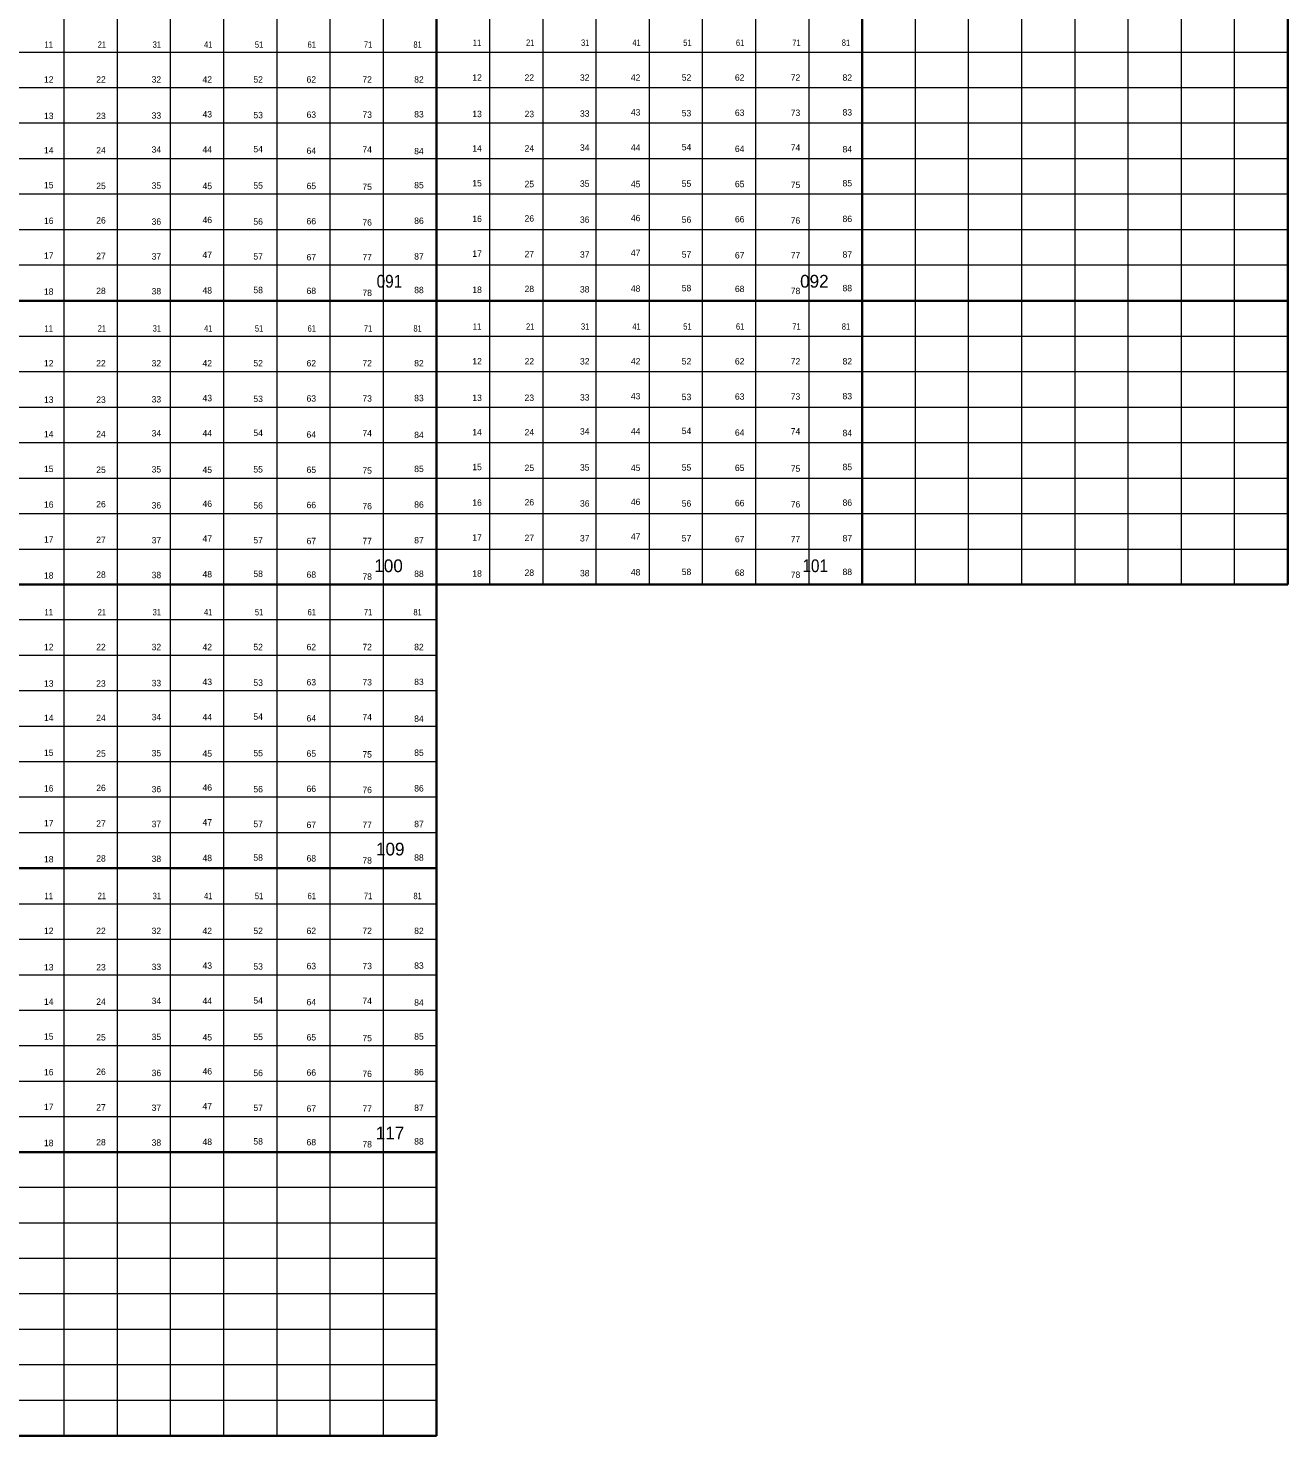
# Model space of a CAD drawing. Extents: x 639000 to 672000, y 222000 to 252000.
# Drawn here: x 660121 to 669000, y 224000 to 233921 of the extents above; entities that cross this region are included whole.
import ezdxf
from ezdxf.enums import TextEntityAlignment as Align

# ---------------------------------------------------------------- set-up
doc = ezdxf.new("R2010")
doc.units = 0
doc.header["$LTSCALE"] = 18
doc.layers.add('1', color=7, linetype='Continuous', lineweight=13)
doc.layers.add('2', color=7, linetype='Continuous')
doc.layers.add('29', color=7, linetype='Continuous')

msp = doc.modelspace()

# ---------------------------------------------------------------- linework, layer by layer
at = {"layer": '1'}
for p, q in [((660375, 224000), (660375, 246000)), ((660750, 224000), (660750, 246000)), ((661125, 224000), (661125, 246000)), ((661500, 224000), (661500, 246000)), ((661875, 224000), (661875, 246000)), ((662250, 224000), (662250, 246000)), ((662625, 224000), (662625, 246000)), ((663375, 230000), (663375, 244000)), ((663750, 230000), (663750, 244000)), ((664125, 230000), (664125, 244000)), ((664500, 230000), (664500, 244000)), ((664875, 230000), (664875, 244000)), ((665250, 230000), (665250, 244000)), ((665625, 230000), (665625, 244000)), ((666375, 230000), (666375, 242000)), ((666750, 230000), (666750, 242000)), ((667125, 230000), (667125, 242000)), ((667500, 230000), (667500, 242000)), ((667875, 230000), (667875, 242000)), ((668250, 230000), (668250, 242000)), ((668625, 230000), (668625, 242000)), ((669000, 233750), (642000, 233750)), ((669000, 233500), (642000, 233500)), ((669000, 233250), (642000, 233250)), ((669000, 233000), (642000, 233000)), ((669000, 232750), (642000, 232750)), ((669000, 232500), (642000, 232500)), ((669000, 232250), (642000, 232250)), ((642000, 231750), (669000, 231750)), ((642000, 231500), (669000, 231500)), ((642000, 231250), (669000, 231250)), ((642000, 231000), (669000, 231000)), ((642000, 230750), (669000, 230750)), ((642000, 230500), (669000, 230500)), ((642000, 230250), (669000, 230250)), ((663000, 229750), (642000, 229750)), ((663000, 229500), (642000, 229500)), ((663000, 229250), (642000, 229250)), ((663000, 229000), (642000, 229000)), ((663000, 228750), (642000, 228750)), ((663000, 228500), (642000, 228500)), ((663000, 228250), (642000, 228250)), ((642000, 227750), (663000, 227750)), ((642000, 227500), (663000, 227500)), ((642000, 227250), (663000, 227250)), ((642000, 227000), (663000, 227000)), ((642000, 226750), (663000, 226750)), ((642000, 226500), (663000, 226500)), ((642000, 226250), (663000, 226250)), ((663000, 225750), (642000, 225750)), ((663000, 225500), (642000, 225500)), ((663000, 225250), (642000, 225250)), ((663000, 225000), (642000, 225000)), ((663000, 224750), (642000, 224750)), ((663000, 224500), (642000, 224500)), ((663000, 224250), (642000, 224250))]:
    msp.add_line(p, q, dxfattribs=at)
at = {"layer": '1', "lineweight": 35}
for p, q in [((663000, 224000), (663000, 246000)), ((666000, 230000), (666000, 244000)), ((669000, 230000), (669000, 242000)), ((669000, 232000), (642000, 232000)), ((642000, 230000), (669000, 230000)), ((663000, 228000), (642000, 228000)), ((642000, 226000), (663000, 226000)), ((663000, 224000), (642000, 224000))]:
    msp.add_line(p, q, dxfattribs=at)

# ---------------------------------------------------------------- texts
at = {"layer": '2', "width": 0.9}
for s, p in [('091', (662667.19, 232091.88)), ('101', (665668.41, 230086.92))]:
    msp.add_text(s, height=90, rotation=359.94, dxfattribs=at).set_placement(p, align=Align.CENTER)
at = {"layer": '2'}
for s, p in [('092', (665662.55, 232091.88)), ('100', (662661.23, 230086.92))]:
    msp.add_text(s, height=90, rotation=359.94, dxfattribs=at).set_placement(p, align=Align.CENTER)
for s, p in [('109', (662673.03, 228090.19)), ('117', (662671.79, 226089.35))]:
    msp.add_text(s, height=90, dxfattribs=at).set_placement(p, align=Align.CENTER)
at = {"layer": '29', "width": 0.85}
for s, p in [('11', (663285.22, 233795.72)), ('21', (663659.82, 233795.72)), ('31', (664047.12, 233795.72)), ('41', (664409.03, 233795.72)), ('51', (664767.76, 233795.72)), ('61', (665139.19, 233795.72)), ('71', (665536.02, 233795.72)), ('81', (665885.22, 233795.72)), ('11', (660265.92, 233782.2)), ('21', (660640.53, 233782.2)), ('31', (661027.83, 233782.2)), ('41', (661389.73, 233782.2)), ('51', (661748.47, 233782.2)), ('61', (662119.89, 233782.2)), ('71', (662516.72, 233782.2)), ('81', (662865.93, 233782.2)), ('11', (660265.92, 231782.2)), ('21', (660640.53, 231782.2)), ('31', (661027.83, 231782.2)), ('41', (661389.73, 231782.2)), ('51', (661748.47, 231782.2)), ('61', (662119.89, 231782.2)), ('71', (662516.72, 231782.2)), ('81', (662865.93, 231782.2)), ('11', (663285.22, 231795.72)), ('21', (663659.82, 231795.72)), ('31', (664047.12, 231795.72)), ('41', (664409.03, 231795.72)), ('51', (664767.76, 231795.72)), ('61', (665139.19, 231795.72)), ('71', (665536.02, 231795.72)), ('81', (665885.22, 231795.72)), ('11', (660265.92, 229782.2)), ('21', (660640.53, 229782.2)), ('31', (661027.83, 229782.2)), ('41', (661389.73, 229782.2)), ('51', (661748.47, 229782.2)), ('61', (662119.89, 229782.2)), ('71', (662516.72, 229782.2)), ('81', (662865.93, 229782.2)), ('11', (660265.92, 227782.2)), ('21', (660640.53, 227782.2)), ('31', (661027.83, 227782.2)), ('41', (661389.73, 227782.2)), ('51', (661748.47, 227782.2)), ('61', (662119.89, 227782.2)), ('71', (662516.72, 227782.2)), ('81', (662865.93, 227782.2))]:
    msp.add_text(s, height=45, dxfattribs=at).set_placement(p, align=Align.CENTER)
at = {"layer": '29'}
for s, p in [('12', (660265.92, 233536.81)), ('22', (660634.18, 233536.81)), ('32', (661024.65, 233536.81)), ('42', (661383.38, 233536.81)), ('52', (661742.11, 233536.81)), ('62', (662116.72, 233536.81)), ('72', (662510.37, 233536.81)), ('82', (662875.45, 233536.81)), ('12', (663285.22, 233550.33)), ('22', (663653.47, 233550.33)), ('32', (664043.95, 233550.33)), ('42', (664402.68, 233550.33)), ('52', (664761.41, 233550.33)), ('62', (665136.01, 233550.33)), ('72', (665529.66, 233550.33)), ('82', (665894.74, 233550.33)), ('43', (661383.39, 233291.42)), ('83', (662875.45, 233291.42)), ('13', (663285.22, 233293.4)), ('23', (663653.47, 233293.4)), ('33', (664043.95, 233296.28)), ('43', (664402.68, 233304.94)), ('53', (664761.41, 233299.17)), ('63', (665136.01, 233302.06)), ('73', (665529.67, 233302.06)), ('83', (665894.74, 233304.94)), ('13', (660265.92, 233279.87)), ('23', (660634.18, 233279.87)), ('33', (661024.65, 233282.76)), ('53', (661742.11, 233285.65)), ('63', (662116.72, 233288.53)), ('73', (662510.37, 233288.53)), ('14', (660265.92, 233037.37)), ('24', (660634.18, 233037.37)), ('34', (661024.65, 233043.14)), ('44', (661383.39, 233043.14)), ('54', (661742.11, 233046.03)), ('64', (662116.72, 233034.48)), ('74', (662510.37, 233043.14)), ('84', (662875.45, 233031.6)), ('14', (663285.22, 233050.89)), ('24', (663653.47, 233050.89)), ('34', (664043.95, 233056.67)), ('44', (664402.68, 233056.67)), ('54', (664761.41, 233059.55)), ('64', (665136.01, 233048.01)), ('74', (665529.67, 233056.67)), ('84', (665894.74, 233045.12)), ('15', (663285.22, 232805.5)), ('25', (663653.47, 232799.73)), ('35', (664043.95, 232802.61)), ('45', (664402.68, 232799.73)), ('55', (664761.41, 232802.61)), ('65', (665136.01, 232799.73)), ('75', (665529.67, 232793.95)), ('85', (665894.74, 232805.5)), ('15', (660265.92, 232791.98)), ('25', (660634.18, 232786.21)), ('35', (661024.65, 232789.09)), ('45', (661383.39, 232786.21)), ('55', (661742.11, 232789.09)), ('65', (662116.72, 232786.21)), ('75', (662510.37, 232780.43)), ('85', (662875.45, 232791.98)), ('16', (660265.92, 232540.82)), ('26', (660634.18, 232543.7)), ('36', (661024.65, 232535.04)), ('46', (661383.39, 232546.59)), ('56', (661742.11, 232535.04)), ('66', (662116.72, 232537.93)), ('76', (662510.37, 232529.27)), ('86', (662875.45, 232540.82)), ('16', (663285.22, 232554.34)), ('26', (663653.47, 232557.22)), ('36', (664043.95, 232548.56)), ('46', (664402.68, 232560.11)), ('56', (664761.41, 232548.56)), ('66', (665136.01, 232551.45)), ('76', (665529.67, 232542.79)), ('86', (665894.74, 232554.34)), ('47', (661383.39, 232301.2)), ('17', (663285.22, 232308.95)), ('27', (663653.47, 232306.06)), ('37', (664043.95, 232303.17)), ('47', (664402.68, 232314.72)), ('57', (664761.41, 232303.17)), ('67', (665136.01, 232297.4)), ('87', (665894.75, 232303.17)), ('17', (660265.92, 232295.43)), ('27', (660634.18, 232292.54)), ('37', (661024.65, 232289.65)), ('57', (661742.12, 232289.65)), ('67', (662116.72, 232283.88)), ('77', (662510.37, 232283.88)), ('87', (662875.45, 232289.65)), ('77', (665529.67, 232297.4)), ('18', (660265.92, 232041.37)), ('28', (660634.18, 232047.15)), ('38', (661024.65, 232044.26)), ('48', (661383.38, 232050.03)), ('58', (661742.11, 232052.92)), ('68', (662116.72, 232047.15)), ('78', (662510.37, 232032.71)), ('88', (662875.45, 232052.92)), ('18', (663285.22, 232054.9)), ('28', (663653.47, 232060.67)), ('38', (664043.95, 232057.78)), ('48', (664402.68, 232063.56)), ('58', (664761.41, 232066.44)), ('68', (665136.01, 232060.67)), ('78', (665529.66, 232046.23)), ('88', (665894.74, 232066.44)), ('12', (660265.92, 231536.81)), ('22', (660634.18, 231536.81)), ('32', (661024.65, 231536.81)), ('42', (661383.38, 231536.81)), ('52', (661742.11, 231536.81)), ('62', (662116.72, 231536.81)), ('72', (662510.37, 231536.81)), ('82', (662875.45, 231536.81)), ('12', (663285.22, 231550.33)), ('22', (663653.47, 231550.33)), ('32', (664043.95, 231550.33)), ('42', (664402.68, 231550.33)), ('52', (664761.41, 231550.33)), ('62', (665136.01, 231550.33)), ('72', (665529.66, 231550.33)), ('82', (665894.74, 231550.33)), ('13', (660265.92, 231279.87)), ('23', (660634.18, 231279.87)), ('33', (661024.65, 231282.76)), ('43', (661383.39, 231291.42)), ('53', (661742.11, 231285.65)), ('63', (662116.72, 231288.53)), ('73', (662510.37, 231288.53)), ('83', (662875.45, 231291.42)), ('13', (663285.22, 231293.4)), ('23', (663653.47, 231293.4)), ('33', (664043.95, 231296.28)), ('43', (664402.68, 231304.94)), ('53', (664761.41, 231299.17)), ('63', (665136.01, 231302.06)), ('73', (665529.67, 231302.06)), ('83', (665894.74, 231304.94)), ('14', (660265.92, 231037.37)), ('24', (660634.18, 231037.37)), ('34', (661024.65, 231043.14)), ('44', (661383.39, 231043.14)), ('54', (661742.11, 231046.03)), ('64', (662116.72, 231034.48)), ('74', (662510.37, 231043.14)), ('84', (662875.45, 231031.6)), ('14', (663285.22, 231050.89)), ('24', (663653.47, 231050.89)), ('34', (664043.95, 231056.67)), ('44', (664402.68, 231056.67)), ('54', (664761.41, 231059.55)), ('64', (665136.01, 231048.01)), ('74', (665529.67, 231056.67)), ('84', (665894.74, 231045.12)), ('15', (660265.92, 230791.98)), ('25', (660634.18, 230786.21)), ('35', (661024.65, 230789.09)), ('45', (661383.39, 230786.21)), ('55', (661742.11, 230789.09)), ('65', (662116.72, 230786.21)), ('75', (662510.37, 230780.43)), ('85', (662875.45, 230791.98)), ('15', (663285.22, 230805.5)), ('25', (663653.47, 230799.73)), ('35', (664043.95, 230802.61)), ('45', (664402.68, 230799.73)), ('55', (664761.41, 230802.61)), ('65', (665136.01, 230799.73)), ('75', (665529.67, 230793.95)), ('85', (665894.74, 230805.5)), ('16', (660265.92, 230540.82)), ('26', (660634.18, 230543.7)), ('36', (661024.65, 230535.04)), ('46', (661383.39, 230546.59)), ('56', (661742.11, 230535.04)), ('66', (662116.72, 230537.93)), ('76', (662510.37, 230529.27)), ('86', (662875.45, 230540.82)), ('16', (663285.22, 230554.34)), ('26', (663653.47, 230557.22)), ('36', (664043.95, 230548.56)), ('46', (664402.68, 230560.11)), ('56', (664761.41, 230548.56)), ('66', (665136.01, 230551.45)), ('76', (665529.67, 230542.79)), ('86', (665894.74, 230554.34)), ('47', (664402.68, 230314.72)), ('17', (660265.92, 230295.43)), ('27', (660634.18, 230292.54)), ('37', (661024.65, 230289.65)), ('47', (661383.39, 230301.2)), ('57', (661742.12, 230289.65)), ('67', (662116.72, 230283.88)), ('77', (662510.37, 230283.88)), ('87', (662875.45, 230289.65)), ('17', (663285.22, 230308.95)), ('27', (663653.47, 230306.06)), ('37', (664043.95, 230303.17)), ('57', (664761.41, 230303.17)), ('67', (665136.01, 230297.4)), ('77', (665529.67, 230297.4)), ('87', (665894.75, 230303.17)), ('18', (660265.92, 230041.37)), ('28', (660634.18, 230047.15)), ('38', (661024.65, 230044.26)), ('48', (661383.38, 230050.03)), ('58', (661742.11, 230052.92)), ('68', (662116.72, 230047.15)), ('78', (662510.37, 230032.71)), ('88', (662875.45, 230052.92)), ('18', (663285.22, 230054.9)), ('28', (663653.47, 230060.67)), ('38', (664043.95, 230057.78)), ('48', (664402.68, 230063.56)), ('58', (664761.41, 230066.44)), ('68', (665136.01, 230060.67)), ('78', (665529.66, 230046.23)), ('88', (665894.74, 230066.44)), ('12', (660265.92, 229536.81)), ('22', (660634.18, 229536.81)), ('32', (661024.65, 229536.81)), ('42', (661383.38, 229536.81)), ('52', (661742.11, 229536.81)), ('62', (662116.72, 229536.81)), ('72', (662510.37, 229536.81)), ('82', (662875.45, 229536.81)), ('13', (660265.92, 229279.87)), ('23', (660634.18, 229279.87)), ('33', (661024.65, 229282.76)), ('43', (661383.39, 229291.42)), ('53', (661742.11, 229285.65)), ('63', (662116.72, 229288.53)), ('73', (662510.37, 229288.53)), ('83', (662875.45, 229291.42)), ('14', (660265.92, 229037.37)), ('24', (660634.18, 229037.37)), ('34', (661024.65, 229043.14)), ('44', (661383.39, 229043.14)), ('54', (661742.11, 229046.03)), ('64', (662116.72, 229034.48)), ('74', (662510.37, 229043.14)), ('84', (662875.45, 229031.6)), ('15', (660265.92, 228791.98)), ('25', (660634.18, 228786.21)), ('35', (661024.65, 228789.09)), ('45', (661383.39, 228786.21)), ('55', (661742.11, 228789.09)), ('65', (662116.72, 228786.21)), ('75', (662510.37, 228780.43)), ('85', (662875.45, 228791.98)), ('16', (660265.92, 228540.82)), ('26', (660634.18, 228543.7)), ('36', (661024.65, 228535.04)), ('46', (661383.39, 228546.59)), ('56', (661742.11, 228535.04)), ('66', (662116.72, 228537.93)), ('76', (662510.37, 228529.27)), ('86', (662875.45, 228540.82)), ('17', (660265.92, 228295.43)), ('27', (660634.18, 228292.54)), ('37', (661024.65, 228289.65)), ('47', (661383.39, 228301.2)), ('57', (661742.12, 228289.65)), ('67', (662116.72, 228283.88)), ('77', (662510.37, 228283.88)), ('87', (662875.45, 228289.65)), ('18', (660265.92, 228041.37)), ('28', (660634.18, 228047.15)), ('38', (661024.65, 228044.26)), ('48', (661383.38, 228050.03)), ('58', (661742.11, 228052.92)), ('68', (662116.72, 228047.15)), ('78', (662510.37, 228032.71)), ('88', (662875.45, 228052.92)), ('12', (660265.92, 227536.81)), ('22', (660634.18, 227536.81)), ('32', (661024.65, 227536.81)), ('42', (661383.38, 227536.81)), ('52', (661742.11, 227536.81)), ('62', (662116.72, 227536.81)), ('72', (662510.37, 227536.81)), ('82', (662875.45, 227536.81)), ('13', (660265.92, 227279.87)), ('23', (660634.18, 227279.87)), ('33', (661024.65, 227282.76)), ('43', (661383.39, 227291.42)), ('53', (661742.11, 227285.65)), ('63', (662116.72, 227288.53)), ('73', (662510.37, 227288.53)), ('83', (662875.45, 227291.42)), ('34', (661024.65, 227043.14)), ('44', (661383.39, 227043.14)), ('54', (661742.11, 227046.03)), ('74', (662510.37, 227043.14)), ('14', (660265.92, 227037.37)), ('24', (660634.18, 227037.37)), ('64', (662116.72, 227034.48)), ('84', (662875.45, 227031.6)), ('15', (660265.92, 226791.98)), ('25', (660634.18, 226786.21)), ('35', (661024.65, 226789.09)), ('45', (661383.39, 226786.21)), ('55', (661742.11, 226789.09)), ('65', (662116.72, 226786.21)), ('75', (662510.37, 226780.43)), ('85', (662875.45, 226791.98)), ('26', (660634.18, 226543.7)), ('46', (661383.39, 226546.59)), ('16', (660265.92, 226540.82)), ('36', (661024.65, 226535.04)), ('56', (661742.11, 226535.04)), ('66', (662116.72, 226537.93)), ('76', (662510.37, 226529.27)), ('86', (662875.45, 226540.82)), ('17', (660265.92, 226295.43)), ('27', (660634.18, 226292.54)), ('37', (661024.65, 226289.65)), ('47', (661383.39, 226301.2)), ('57', (661742.12, 226289.65)), ('67', (662116.72, 226283.88)), ('77', (662510.37, 226283.88)), ('87', (662875.45, 226289.65)), ('28', (660634.18, 226047.15)), ('48', (661383.38, 226050.03)), ('58', (661742.11, 226052.92)), ('68', (662116.72, 226047.15)), ('88', (662875.45, 226052.92)), ('18', (660265.92, 226041.37)), ('38', (661024.65, 226044.26)), ('78', (662510.37, 226032.71))]:
    msp.add_text(s, height=45, dxfattribs=at).set_placement(p, align=Align.CENTER)

doc.saveas('drawing.dxf')
